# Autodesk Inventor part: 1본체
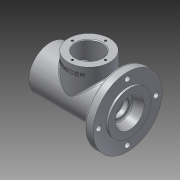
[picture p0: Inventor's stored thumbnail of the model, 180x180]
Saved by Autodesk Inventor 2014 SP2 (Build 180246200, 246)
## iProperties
Created: 2016-08
Part Number: 1본체
Material: 알루미늄 6061
Document SubType Name: Modeling
Designer: 달림반
Density: 2.71 g/cm^3
Appearance: 알루미늄 - 평지
Author: 달림반
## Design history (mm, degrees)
sketch "스케치1"
  geometry: L1 (0, 0)-(115, 0); L2 (0, 21)-(9, 21); L3 (9, 21)-(9, 24); L4 (9, 24)-(12, 24); L5 (12, 24)-(12, 20); L6 (12, 20)-(21, 20); L7 (21, 20)-(21, 17.5); L8 (21, 17.5)-(24.25, 17.5); L9 (24.25, 17.5)-(24.25, 18.5); L10 (24.25, 18.5)-(26, 18.5); L11 (26, 18.5)-(26, 17.5); L12 (26, 17.5)-(37, 17.5); L13 (37, 17.5)-(37, 26); L14 (37, 26)-(75, 26); L15 (75, 26)-(75, 17.5); L16 (75, 17.5)-(86, 17.5); L17 (86, 17.5)-(86, 16.5); L18 (86, 16.5)-(91, 16.5); L19 (91, 16.5)-(91, 10); L20 (91, 10)-(93.7, 10); L21 (93.7, 10)-(93.7, 12.5); L22 (93.7, 12.5)-(101, 12.5); L23 (101, 12.5)-(101, 16); L24 (101, 16)-(115, 21); L25 (115, 21)-(115, 31); L26 (115, 31)-(112, 31); L27 (112, 31)-(112, 50); L28 (112, 50)-(99, 50); L29 (99, 50)-(99, 31); L30 (99, 31)-(0, 31); L31 (0, 31)-(0, 21)
  constraints: 62 end point, 28 parallel, 2 vertical alignment, 1 collinear, 1 horizontal, 1 perpendicular
  dimensions: "d0" = 115 distance between parallel lines of L25 L31; "d1" = 3 distance of L25.end L26.end; "d2" = 13 distance of L27.end L28.end; "d3" = 100 diameter of L28 L1; "d4" = 62 diameter of L26 L1; "d5" = 42 diameter of L24.end L1; "d6" = 32 diameter of L23.end L1; "d7" = 25 diameter of L22 L1; "d8" = 20 diameter of L20 L1; "d9" = 33 diameter of L18 L1; "d10" = 35 diameter of L16 L1; "d11" = 52 diameter of L14 L1; "d12" = 35 diameter of L12 L1; "d13" = 37 diameter of L10 L1; "d14" = 35 diameter of L8 L1; "d15" = 40 diameter of L6 L1; "d16" = 48 diameter of L4 L1; "d17" = 42 diameter of L2 L1; "d18" = 62 diameter of L30 L1; "d19" = 14 distance between parallel lines of L25 L23; "d20" = 2.7 distance of L19.end L20.end; "d21" = 7.3 distance of L21.end L22.end; "d22" = 38 distance of L13.end L14.end; "d23" = 3 distance of L4.end L3.end; "d24" = 12 distance between parallel lines of L5 L31; "d25" = 21 distance between parallel lines of L7 L31; "d26" = 26 distance between parallel lines of L31 L11; "d27" = 1.75 distance of L9.end L10.end; "d28" = 5 distance between parallel lines of L17 L19
revolve "회전1" sketch "스케치1" stored, may be unused: angle "d29" = 90 deg
chamfer "모따기1" distance "d38" = 1; stored, may be unused: second distance "d39" = 2, angle "d40" = 45 deg
node "작업 평면1"
sketch "스케치7"
  geometry: C1 r 30 at (-56, 0); C2 r 19 at (-56, 0); 1 further point
  constraints: 2 centre point, 1 coincident, 1 horizontal alignment
  dimensions: "d43" = 60 diameter of C1; "d44" = 56 distance of point (0, 0) C1.centre; "d45" = 38 diameter of C2
extrude "돌출2" join sketch "스케치7" stored distance "d46" = 40; taper "d47" = 0 deg
sketch "스케치8"
  geometry: C1 r 19 at (0, 0) reference; 1 further point
extrude "돌출3" cut sketch "스케치8" distance "d48" = 40; taper "d49" = 0 deg
chamfer "모따기2" distance "d50" = 1; stored, may be unused: second distance "d51" = 2, angle "d52" = 45 deg
feature "스레드1" dims "d53" = 10, "d54" = 0
chamfer "모따기3" distance "d55" = 1; stored, may be unused: second distance "d56" = 2, angle "d57" = 45 deg
sketch "스케치9"
  geometry: C1 r 30 at (0, 0) reference; C2 r 20 at (0, 0) reference; A1 r 24 centre (0, 0) between (0, 24) and (24, 0); 3 further points
  constraints: 4 point on circle, 2 horizontal alignment, 2 vertical alignment, 1 centre point, 1 coincident
  dimensions: "d58" = 48 diameter of A1
hole "구멍1" sketch "스케치9" at (0, 24), (24, 0), (0, -24), (-24, 0) diameter "d59" = 3.242; stored, may be unused: countersink angle "d63" = 90 deg, drill point angle "d65" = 118 deg; dims "d60" = 8, "d61" = 4, "d62" = 2, "d64" = 10
sketch "스케치10"
  geometry: C1 r 50 at (0, 0) reference; C2 r 31 at (0, 0) reference; A1 r 41.5 centre (0, 0) between (0, 41.5) and (41.5, 0); 2 further points
  constraints: 4 point on circle, 2 horizontal alignment, 2 vertical alignment, 1 centre point, 1 coincident
  dimensions: "d66" = 83 diameter of A1
hole "구멍2" sketch "스케치10" at (0, 41.5), (41.5, 0), (0, -41.5), (-41.5, 0) diameter "d67" = 8; stored, may be unused: countersink angle "d71" = 90 deg, drill point angle "d73" = 118 deg; dims "d68" = 8, "d69" = 4, "d70" = 2, "d72" = 20
sketch "스케치11"
  geometry: L1 (101, 12.904)-(100.3, 12.5); L2 (101, 12.5)-(93.7, 12.5) reference; L3 (101, -16)-(101, 16) reference; L4 (0, 0)-(60.979, 0)
  constraints: 4 end point, 2 point on line, 1 perpendicular
  dimensions: "d74" = 30 deg angle of L2 L1; "d75" = 0.7 distance from line of L3 L1.end
revolve "회전3" sketch "스케치11" stored, may be unused: angle "d76" = 90 deg
fillet "모깎기1" dims "d77" = 0.3
fillet "모깎기2" dims "d78" = 3
fillet "모깎기3" dims "d79" = 3
fillet "모깎기4" dims "d80" = 3
node "작업 평면2"
sketch "스케치13"
  geometry: L1 (0, -31)-(0, 31) reference; L2 (26, 49)-(86, 49) reference; 2 further points
  constraints: 1 other
  dimensions: "d82" = 56 distance from line of L1 point (56, 39); "d83" = 10 distance from line of L2 point (56, 39)
feature "엠보싱1" sketch "스케치13" dims "d84" = 0.5, "d85" = 0
fillet "모깎기6" dims "d87" = 3
node "솔리드1"
other parameters: "d42" = 49, "d81" = 84.75
